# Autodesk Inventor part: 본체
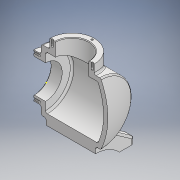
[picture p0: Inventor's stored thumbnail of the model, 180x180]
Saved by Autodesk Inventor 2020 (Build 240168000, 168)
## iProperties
Created: 2023-12
Part Number: 본체
Material: 일반
Document SubType Name: Modeling
Designer: 1강의실14
Density: 1 g/cm^3
Appearance: 기본값
Author: 1강의실14
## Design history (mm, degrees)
sketch "스케치1"
  geometry: L1 (-48.168, -50)-(48.168, -50); L2 (48.168, -50)-(48.168, 50); L3 (48.168, 50)-(-48.168, 50); L4 (-48.168, 50)-(-48.168, -50); L5 (-48.168, -50)-(48.168, 50); L6 (48.168, -50)-(-48.168, 50); L7 (-48.168, 0)-(59.832, 0); A1 r 113 centre (-53.168, 0) between (48.168, -50) and (48.168, 50); 1 further point
  constraints: 14 end point, 3 midpoint, 3 point on circle, 2 parallel, 1 centre point, 1 horizontal, 1 perpendicular
  dimensions: "d0" = 100 distance of L3.end L1.start; "d3" = 113 radius of A1; "d4" = 108 horizontal distance of L3.end L7.end
revolve "회전1" sketch "스케치1" stored, may be unused: angle "d5" = 90 deg
feature "쉘1" dims "d9" = 7
sketch "스케치2"
  geometry: C1 r 36 at (0, 0); 1 further point
  constraints: 1 centre point, 1 coincident
  dimensions: "d6" = 72 diameter of C1
extrude "돌출1" join sketch "스케치2" distance "d7" = 12; taper "d8" = 0 deg
sketch "스케치4"
  geometry: C1 r 27 at (0, 0); 1 further point
  constraints: 1 centre point, 1 coincident
  dimensions: "d11" = 54 diameter of C1
extrude "돌출2" cut sketch "스케치4" distance "d12" = 19; taper "d13" = 0 deg
sketch "스케치5"
  geometry: L1 (0, 0)-(0, 32.5)
  constraints: 2 end point, 1 vertical
  dimensions: "d14" = 32.5 distance of L1.start L1.end
hole "구멍1" sketch "스케치5" at (0, 32.5) diameter "d15" = 3.242; stored, may be unused: countersink angle "d19" = 90 deg, drill point angle "d21" = 118 deg; dims "d16" = 8, "d17" = 4, "d18" = 2, "d20" = 10
node "작업 평면1"
sketch "스케치7" dims "d11" = 54
  geometry: L1 (40.168, -62)-(-39.832, -62); L2 (-39.832, -62)-(-39.832, 62); L3 (-39.832, 62)-(40.168, 62); L4 (40.168, 62)-(40.168, -62); L5 (40.168, -62)-(-39.832, 62); L6 (-39.832, -62)-(40.168, 62); L7 (60.168, -36)-(60.168, 36) reference; 3 further points
  constraints: 12 end point, 4 midpoint, 2 parallel, 1 horizontal, 1 horizontal alignment, 1 perpendicular
  dimensions: "d26" = 124 distance of L1.end L2.end; "d27" = 80 distance of L2.end L3.end; "d82" = 20 distance between parallel lines of L7 L4
extrude "돌출3" join sketch "스케치7" distance "d28" = 10; taper "d29" = 0 deg
node "작업 평면2"
sketch "스케치8"
  geometry: L1 (-60.168, 36)-(-60.168, -36) reference; C1 r 36 at (1.832, 0); 1 further point
  constraints: 1 centre point, 1 horizontal alignment
  dimensions: "d31" = 72 diameter of C1; "d32" = 62 distance from line of L1 C1.centre
extrude "돌출4" join sketch "스케치8" stored distance "d33" = 10; taper "d34" = 0 deg
sketch "스케치9"
  geometry: C1 r 36 at (0, 0) reference; C2 r 27 at (0, 0); 1 further point
  constraints: 1 centre point, 1 coincident
  dimensions: "d35" = 54 diameter of C2
extrude "돌출5" cut sketch "스케치9" distance "d36" = 75.5; taper "d37" = 0 deg
sketch "스케치10"
  geometry: L1 (0, 0)-(32.5, 0); L2 (-43, 43)-(41.887, 43) reference; C1 r 27 at (0, 0) reference; C2 r 36 at (0, 0) reference; 1 further point
  constraints: 2 end point, 1 parallel
  dimensions: "d38" = 32.5 distance of L1.start L1.end
hole "구멍2" sketch "스케치10" at (32.5, 0) diameter "d39" = 3.242; stored, may be unused: countersink angle "d43" = 90 deg, drill point angle "d45" = 118 deg; dims "d40" = 8, "d41" = 4, "d42" = 2, "d44" = 10
sketch "스케치11"
  geometry: L1 (-67, 62)-(-67, -62) reference; L2 (-42.278, -26.694)-(-67, -62); L3 (-42.278, 26.694)-(-67, 62); L4 (-77, 62)-(-67, 62) reference; L5 (-77, -62)-(-67, -62) reference; A1 r 50 centre (0, 0) between (-42.278, -26.694) and (-42.278, 26.694) reference; 1 further point
  constraints: 4 end point, 2 point on circle
  dimensions: "d49" = 55 deg angle of L4 L3; "d51" = 55 deg angle of L5 L2
extrude "돌출6" join sketch "스케치11" stored distance "d52" = 80; taper "d53" = 0 deg
sketch "스케치12"
  geometry: L1 (124, 0)-(0, 0) reference; L2 (62, 0)-(62, 17); A1 r 52.096 centre (62, -35.096) between (100.5, 0) and (23.5, 0); 1 further point
  constraints: 3 point on circle, 2 end point, 2 point on line, 1 centre point, 1 midpoint, 1 vertical alignment
  dimensions: "d54" = 17 distance of L2.start L2.end; "d55" = 77 distance of A1.end A1.start
extrude "돌출7" cut sketch "스케치12" extent not by distance; stored distance "d56" = 0; taper "d57" = 0 deg
sketch "스케치14"
  geometry: L1 (-20.168, 62)-(-20.168, 54); L2 (-40.168, 62)-(39.832, 62) reference; L3 (-40.168, 38.5)-(-40.168, 62) reference; L4 (-40.168, 62)-(39.832, 62) reference; L5 (19.832, 62)-(19.832, 54); L6 (39.832, 62)-(39.832, 38.5) reference; C1 r 4.5 at (-20.168, 54); C2 r 4.5 at (19.832, 54); 1 further point
  constraints: 4 end point, 2 centre point, 2 coincident, 2 point on line, 2 vertical
  dimensions: "d58" = 8 distance of L1.start L1.end; "d59" = 20 distance between parallel lines of L3 L1; "d60" = 9 diameter of C1; "d61" = 8 distance of L5.start L5.end; "d62" = 20 distance between parallel lines of L6 L5; "d63" = 9 diameter of C2
extrude "돌출8" cut sketch "스케치14" distance "d64" = 42.5; taper "d65" = 0 deg
node "작업 평면3"
sketch "스케치15"
  geometry: L1 (-27.168, 54)-(-27.168, 62.253); L2 (-40, 62)-(39.832, 62) reference; L3 (-13.168, 54)-(-13.168, 62); L4 (12.832, 54)-(12.832, 62); L5 (26.832, 54)-(26.832, 62); C1 r 4.5 at (-20.168, 54) reference; C2 r 4.5 at (19.832, 54) reference; A1 r 7 centre (-20.168, 54) between (-27.168, 54) and (-13.168, 54); A2 r 7 centre (19.832, 54) between (12.832, 54) and (26.832, 54); 3 further points
  constraints: 8 end point, 4 point on circle, 3 point on line, 3 tangent, 2 centre point, 2 coincident, 2 perpendicular, 2 vertical, 1 horizontal alignment
  dimensions: "d67" = 14 diameter of A1; "d68" = 14 diameter of A2
extrude "돌출9" cut sketch "스케치15" distance "d69" = 26; taper "d70" = 0 deg
node "작업 평면4"
sketch "스케치16"
  geometry: L1 (-60.168, 36)-(-60.168, -36) reference; 2 further points
  constraints: 1 horizontal alignment, 1 other
  dimensions: "d71" = 62 distance from line of L1 point (1.832, 0)
feature "엠보싱1" sketch "스케치16" dims "d11" = 54, "d72" = 0.5, "d73" = 0
chamfer "모따기1" distance "d74" = 1; stored, may be unused: second distance "d75" = 2, angle "d76" = 45 deg
fillet "모깎기1" dims "d77" = 3
sketch "스케치17"
  geometry: L1 (-26.694, -42.278)-(-62, -67) reference; L2 (62, -67)-(26.083, -67) reference; L3 (-26.083, -67)-(-62, -67) reference; L4 (62, -67)-(26.694, -42.278) reference; A1 r 52.096 centre (0, -112.096) between (26.083, -67) and (-26.083, -67) reference; A2 r 50 centre (0, 0) between (-26.694, -42.278) and (26.694, -42.278) reference; 1 further point
  node "투영된 루프4"
sketch "스케치18"
  geometry: 1 further point
extrude "돌출10" join sketch "스케치17" stored distance "d83" = 10; taper "d84" = 0 deg
sketch "스케치19"
  geometry: L1 (26.083, -67)-(62, -67) reference; L2 (62, -67)-(26.694, -42.278) reference; L3 (-26.694, -42.278)-(-62, -67) reference; L4 (-62, -67)-(-26.083, -67) reference; A1 r 52.096 centre (0, -112.096) between (26.083, -67) and (-26.083, -67) reference; A2 r 50 centre (0, 0) between (-26.694, -42.278) and (26.694, -42.278) reference; 1 further point
extrude "돌출11" cut sketch "스케치19" stored distance "d85" = 10; taper "d86" = 0 deg
fillet "모깎기5" dims "d87" = 3
fillet "모깎기6" dims "d88" = 3
fillet "모깎기7" dims "d89" = 3
feature "분할1"
node "솔리드1"
pattern_circular "원형 패턴1" dims angle "d23" = 360 deg
pattern_circular "원형 패턴2" dims angle "d47" = 360 deg
mirror "미러1"
node "투영된 루프2"
node "투영된 루프3"
node "투영된 루프5"
feature "A9D066F2-1C7D-4E18-AEED-F7BC21143FA4" dims "d15" = 3.242, "d16" = 8, "d17" = 4, "d18" = 2, "d19" = 90 deg, "d20" = 10, "d21" = 118 deg
other parameters: "d25" = -77, "d30" = -142, "d66" = -6
